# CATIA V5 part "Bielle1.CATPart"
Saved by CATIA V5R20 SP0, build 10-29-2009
Part number: Bielle1
Bounding box of the stored display mesh (mm): x 0 to 50, y -117.046 to 181.669, z -0.808 to 19.191
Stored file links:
  D:\Dropbox\IAO_2011\MMS_GR1\abruchon\abruchon\Bielle1.CATPart
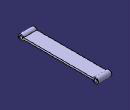
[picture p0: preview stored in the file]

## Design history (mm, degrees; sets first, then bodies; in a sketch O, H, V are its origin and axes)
Body1 (main body)
  Sketch1 on yz-plane, origin (0, 0, 0), H (0, 1, 0), V (0, 0, 1)
    line L1 (-97.6882, 12.6779) -> (162.3118, 12.6779)
    line L2 (162.3118, 5.705) -> (-97.6882, 5.705)
    arc A1 centre (171.6843, 9.1915) radius 10 from (162.3118, 12.6779) to (162.3118, 5.705) cw
    arc A2 centre (-107.0608, 9.1915) radius 10 from (-97.6882, 12.6779) to (-97.6882, 5.705) ccw
    point P7 (-111, 0)
    circle A3 centre (171.6843, 9.1915) radius 6
    circle A4 centre (-107.0608, 9.1915) radius 6
    radius A2 = 10
    length L1 = 260
    length L2 = 260
    horizontal: L1 H, L2 H
    coincidence: A2 P7, P7 H
  Pad1: profile Sketch1, direction (1, 0, 0), length 50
